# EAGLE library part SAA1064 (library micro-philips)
I2C-Bus 4-digit LED-DRIVER
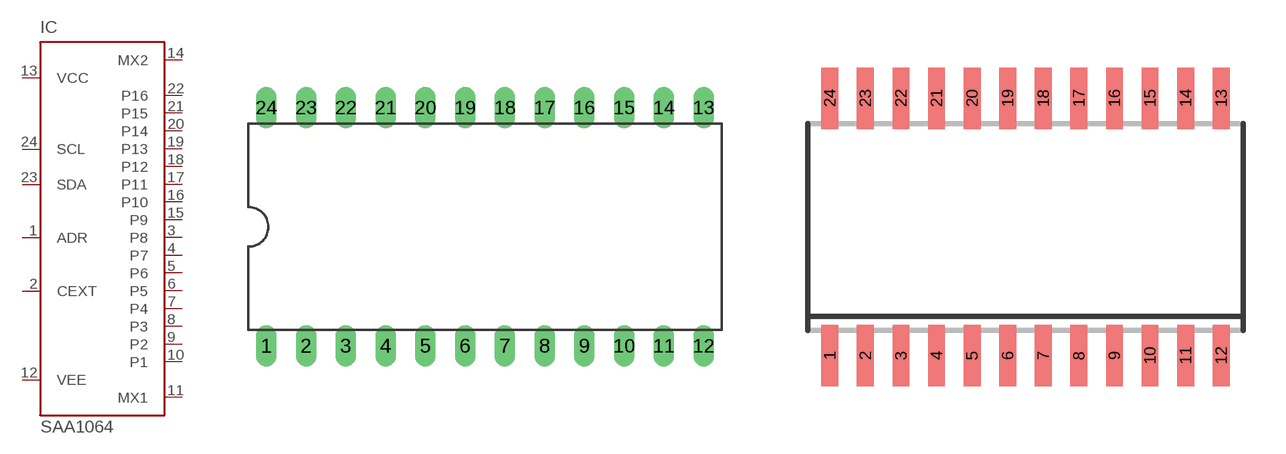
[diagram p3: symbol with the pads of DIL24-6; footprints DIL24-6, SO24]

Designator prefix IC

## SAA1064 (MPN: SAA1064/N2,112; OC_FARNELL: 1627002; OC_NEWARK: 70R8646)  [DIL24-6]
1  ADR  in
2  CEXT  in
3  P8  out
4  P7  out
5  P6  out
6  P5  out
7  P4  out
8  P3  out
9  P2  out
10  P1  out
11  MX1  out
12  VEE  pwr
13  VCC  pwr
14  MX2  out
15  P9  out
16  P10  out
17  P11  out
18  P12  out
19  P13  out
20  P14  out
21  P15  out
22  P16  out
23  SDA  in
24  SCL  in

## SAA1064T (MPN: SAA1064T/N2,118; OC_FARNELL: unknown; OC_NEWARK: 70R8648)  [SO24]
Pads as for DIL24-6

## Footprint DIL24-6 (pad centres in mm)
Dual In Line
drill 0.813 long: 1 -13.97,-7.62; 2 -11.43,-7.62; 3 -8.89,-7.62; 4 -6.35,-7.62; 5 -3.81,-7.62; 6 -1.27,-7.62; 7 1.27,-7.62; 8 3.81,-7.62; 9 6.35,-7.62; 10 8.89,-7.62; 11 11.43,-7.62; 12 13.97,-7.62; 13 13.97,7.62; 14 11.43,7.62; 15 8.89,7.62; 16 6.35,7.62; 17 3.81,7.62; 18 1.27,7.62; 19 -1.27,7.62; 20 -3.81,7.62; 21 -6.35,7.62; 22 -8.89,7.62; 23 -11.43,7.62; 24 -13.97,7.62

## Footprint SO24 (pad centres in mm)
Small Outline Package 7.6 x 15.74 mm
smd 0.6 x 2.2: 1 -6.985,-4.6; 2 -5.715,-4.6; 3 -4.445,-4.6; 4 -3.175,-4.6; 5 -1.905,-4.6; 6 -0.635,-4.6; 7 0.635,-4.6; 8 1.905,-4.6; 9 3.175,-4.6; 10 4.445,-4.6; 11 5.715,-4.6; 12 6.985,-4.6; 13 6.985,4.6; 14 5.715,4.6; 15 4.445,4.6; 16 3.175,4.6; 17 1.905,4.6; 18 0.635,4.6; 19 -0.635,4.6; 20 -1.905,4.6; 21 -3.175,4.6; 22 -4.445,4.6; 23 -5.715,4.6; 24 -6.985,4.6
